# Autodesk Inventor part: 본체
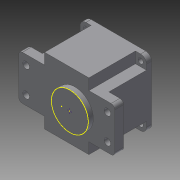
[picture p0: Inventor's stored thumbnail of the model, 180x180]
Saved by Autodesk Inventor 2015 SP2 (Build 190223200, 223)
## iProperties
Created: 2015-06
Part Number: 본체
Material: 일반
Document SubType Name: Modeling
Designer: AMC
Density: 1 g/cm^3
Appearance: 기본값
Author: AMC
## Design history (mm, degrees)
sketch "스케치3"
  geometry: L1 (30, 45)-(-30, 45); L2 (-65, 30)-(-65, -30); L3 (-30, -45)-(30, -45); L4 (65, -30)-(65, 30); L5 (30, 45)-(30, 30); L6 (30, 30)-(65, 30); L7 (65, -30)-(30, -30); L8 (30, -30)-(30, -45); L9 (-30, -45)-(-30, -30); L10 (-30, -30)-(-65, -30); L11 (-30, 45)-(-30, 30); L12 (-30, 30)-(-65, 30); 5 further points
  constraints: 24 end point, 6 point on line, 4 midpoint, 4 parallel, 3 perpendicular, 2 horizontal alignment, 2 vertical alignment, 1 collinear, 1 horizontal, 1 vertical
  dimensions: "d10" = 60 distance of L1.start L1.end; "d11" = 60 distance of L3.start L3.end; "d12" = 60 distance of L4.start L4.end; "d14" = 15 distance of L1.start L5.end; "d16" = 15 distance of L7.end L3.end; "d17" = 130 distance between parallel lines of L2 L4
extrude "돌출3" new body sketch "스케치3" distance "d18" = 12; taper "d19" = 0 deg
sketch "스케치4"
  geometry: L1 (-45, 45)-(45, 45); L2 (45, 45)-(45, -45); L3 (45, -45)-(-45, -45); L4 (-45, -45)-(-45, 45); 3 further points
  constraints: 8 end point, 2 midpoint, 2 parallel, 1 horizontal, 1 horizontal alignment, 1 perpendicular, 1 vertical alignment
  dimensions: "d21" = 90 distance of L3.end L1.start; "d22" = 90 distance of L1.start L1.end
extrude "돌출4" join sketch "스케치4" distance "d23" = 51; taper "d24" = 0 deg
sketch "스케치5"
  geometry: L1 (-45, 45)-(45, 45); L2 (45, 45)-(45, -45); L3 (45, -45)-(-45, -45); L4 (-45, -45)-(-45, 45); 3 further points
  constraints: 8 end point, 2 midpoint, 2 parallel, 1 horizontal, 1 horizontal alignment, 1 perpendicular, 1 vertical alignment
  dimensions: "d25" = 90 distance of L1.start L1.end; "d26" = 90 distance of L3.end L1.start
extrude "돌출5" join sketch "스케치5" distance "d27" = 7; taper "d28" = 0 deg
fillet "모깎기2" dims "d30" = 5
sketch "스케치6"
  geometry: L1 (-30, 45)-(30, 45) reference; L2 (45, 30)-(60, 30) reference; L3 (65, 25)-(65, -25) reference; L4 (60, -30)-(45, -30) reference; L5 (30, -45)-(-30, -45) reference; L6 (-45, -30)-(-60, -30) reference; L7 (-65, -25)-(-65, 25) reference; L8 (-60, 30)-(-45, 30) reference; L9 (-45, -45)-(-45, -30) reference; L10 (-30, -30)-(-45, -30) reference; L11 (-30, -45)-(-30, -30) reference; L12 (30, -30)-(30, -45) reference; L13 (45, -30)-(30, -30) reference; L14 (45, -30)-(45, -45) reference; L15 (45, -45)-(30, -45) reference; L16 (-30, -45)-(-45, -45) reference; L17 (-45, -30)-(-45, 30) reference; L18 (45, 30)-(45, -30) reference; L19 (30, 30)-(45, 30) reference; L20 (30, 45)-(30, 30) reference; L21 (-30, 30)-(-30, 45) reference; L22 (-45, 30)-(-30, 30) reference; L23 (-45, 30)-(-45, 45) reference; L24 (-45, 45)-(-30, 45) reference; L25 (45, 45)-(45, 30) reference; L26 (30, 45)-(45, 45) reference; C1 r 4.5 at (55, 17.5); A1 r 5 centre (60, 25) between (65, 25) and (60, 30) reference; A2 r 5 centre (60, -25) between (60, -30) and (65, -25) reference; A3 r 5 centre (-60, -25) between (-65, -25) and (-60, -30) reference; A4 r 5 centre (-60, 25) between (-60, 30) and (-65, 25) reference; 1 further point
  constraints: 1 centre point
  dimensions: "d32" = 9 diameter of C1; "d33" = 10 distance from line of L3 C1.centre; "d34" = 12.5 distance from line of L2 C1.centre
extrude "돌출6" cut sketch "스케치6" stored distance "d35" = 7; taper "d36" = 0 deg
sketch "스케치7"
  geometry: L1 (-45, -45)-(-45, 45) reference; L2 (-45, 45)-(45, 45) reference; L3 (45, 45)-(45, -45) reference; L4 (45, -45)-(-45, -45) reference; C1 r 3.5 at (37, 37); 2 further points
  constraints: 1 centre point, 1 coincident
  dimensions: "d37" = 7 diameter of C1
extrude "돌출7" cut sketch "스케치7" distance "d38" = 20; taper "d39" = 0 deg
sketch "스케치10"
  geometry: 2 further points
  constraints: 1 coincident
hole "구멍1" sketch "스케치10" at (0, 0) diameter "d48" = 78; stored, may be unused: countersink angle "d52" = 90 deg, drill point angle "d54" = 0 deg; dims "d49" = 6, "d50" = 80, "d51" = 9, "d53" = 61
sketch "스케치11"
  geometry: L1 (-45, -45)-(-45, -30) reference; L2 (-30, -30)-(-45, -30) reference; L3 (-30, -45)-(-30, -30) reference; L4 (30, -45)-(-30, -45) reference; L5 (30, -30)-(30, -45) reference; L6 (45, -30)-(30, -30) reference; L7 (45, -30)-(45, -45) reference; L8 (45, -45)-(30, -45) reference; L9 (-30, -45)-(-45, -45) reference; L10 (-45, -30)-(-45, 30) reference; L11 (-60, 30)-(-45, 30) reference; L12 (-65, -25)-(-65, 25) reference; L13 (-45, -30)-(-60, -30) reference; L14 (60, -30)-(45, -30) reference; L15 (45, 30)-(45, -30) reference; L16 (30, 30)-(45, 30) reference; L17 (30, 45)-(30, 30) reference; L18 (30, 45)-(45, 45) reference; L19 (45, 45)-(45, 30) reference; L20 (45, 30)-(60, 30) reference; L21 (65, 25)-(65, -25) reference; L22 (-45, 30)-(-45, 45) reference; L23 (-45, 45)-(-30, 45) reference; L24 (-30, 45)-(30, 45) reference; L25 (-45, 30)-(-30, 30) reference; L26 (-30, 30)-(-30, 45) reference; L27 (-45, 45)-(-30, 45); L28 (-30, 45)-(-30, 30); L29 (-30, 30)-(-45, 30); L30 (-45, 30)-(-45, 45); C1 r 39 at (0, 0) reference; C2 r 4.5 at (-55, 17.5) reference; C3 r 4.5 at (-55, -17.5) reference; C4 r 4.5 at (55, 17.5) reference; C5 r 4.5 at (55, -17.5) reference; A1 r 5 centre (-60, 25) between (-60, 30) and (-65, 25) reference; A2 r 5 centre (-60, -25) between (-65, -25) and (-60, -30) reference; A3 r 5 centre (60, 25) between (65, 25) and (60, 30) reference; A4 r 5 centre (60, -25) between (60, -30) and (65, -25) reference; 1 further point
  constraints: 8 end point, 2 parallel, 1 horizontal, 1 perpendicular
extrude "돌출9" cut sketch "스케치11" distance "d55" = 51; taper "d56" = 0 deg
sketch "스케치13"
  geometry: L1 (-45, -45)-(-45, -30) reference; L2 (-30, -30)-(-45, -30) reference; L3 (-30, -45)-(-30, -30) reference; L4 (30, -45)-(-30, -45) reference; L5 (30, -30)-(30, -45) reference; L6 (45, -30)-(30, -30) reference; L7 (45, -30)-(45, -45) reference; L8 (45, -45)-(30, -45) reference; L9 (-30, -45)-(-45, -45) reference; L10 (-45, -30)-(-45, 30) reference; L11 (-60, 30)-(-45, 30) reference; L12 (-65, -25)-(-65, 25) reference; L13 (-45, -30)-(-60, -30) reference; L14 (60, -30)-(45, -30) reference; L15 (45, 30)-(45, -30) reference; L16 (30, 30)-(45, 30) reference; L17 (30, 45)-(30, 30) reference; L18 (-30, 45)-(30, 45) reference; L19 (-30, 30)-(-30, 45) reference; L20 (-45, 30)-(-30, 30) reference; L21 (65, 25)-(65, -25) reference; L22 (45, 30)-(60, 30) reference; L23 (45, 45)-(45, 30) reference; L24 (30, 45)-(45, 45) reference; L25 (30, 45)-(45, 45); L26 (45, 45)-(45, 30); L27 (45, 30)-(30, 30); L28 (30, 30)-(30, 45); C1 r 39 at (0, 0) reference; C2 r 4.5 at (-55, 17.5) reference; C3 r 4.5 at (-55, -17.5) reference; C4 r 4.5 at (55, 17.5) reference; C5 r 4.5 at (55, -17.5) reference; A1 r 5 centre (-60, 25) between (-60, 30) and (-65, 25) reference; A2 r 5 centre (-60, -25) between (-65, -25) and (-60, -30) reference; A3 r 5 centre (60, -25) between (60, -30) and (65, -25) reference; A4 r 5 centre (60, 25) between (65, 25) and (60, 30) reference; 1 further point
  constraints: 8 end point, 2 parallel, 1 horizontal, 1 perpendicular
extrude "돌출10" cut sketch "스케치13" distance "d57" = 51; taper "d58" = 0 deg
sketch "스케치14"
  geometry: L1 (-45, -45)-(-45, -30) reference; L2 (-30, -30)-(-45, -30) reference; L3 (-30, -45)-(-30, -30) reference; L4 (30, -45)-(-30, -45) reference; L5 (30, -30)-(30, -45) reference; L6 (45, -30)-(30, -30) reference; L7 (45, -30)-(45, -45) reference; L8 (45, -45)-(30, -45) reference; L9 (-30, -45)-(-45, -45) reference; L10 (-45, -30)-(-45, 30) reference; L11 (-60, 30)-(-45, 30) reference; L12 (-65, -25)-(-65, 25) reference; L13 (-45, -30)-(-60, -30) reference; L14 (60, -30)-(45, -30) reference; L15 (45, 30)-(45, -30) reference; L16 (30, 30)-(45, 30) reference; L17 (30, 45)-(30, 30) reference; L18 (-30, 45)-(30, 45) reference; L19 (-30, 30)-(-30, 45) reference; L20 (-45, 30)-(-30, 30) reference; L21 (65, 25)-(65, -25) reference; L22 (45, 30)-(60, 30) reference; L23 (-45, -30)-(-30, -30); L24 (-30, -30)-(-30, -45); L25 (-30, -45)-(-45, -45); L26 (-45, -45)-(-45, -30); L27 (30, -30)-(45, -30); L28 (45, -30)-(45, -45); L29 (45, -45)-(30, -45); L30 (30, -45)-(30, -30); C1 r 39 at (0, 0) reference; C2 r 4.5 at (-55, 17.5) reference; C3 r 4.5 at (-55, -17.5) reference; C4 r 4.5 at (55, 17.5) reference; C5 r 4.5 at (55, -17.5) reference; A1 r 5 centre (-60, 25) between (-60, 30) and (-65, 25) reference; A2 r 5 centre (-60, -25) between (-65, -25) and (-60, -30) reference; A3 r 5 centre (60, -25) between (60, -30) and (65, -25) reference; A4 r 5 centre (60, 25) between (65, 25) and (60, 30) reference; 1 further point
  constraints: 16 end point, 4 parallel, 2 horizontal, 2 perpendicular
extrude "돌출11" cut sketch "스케치14" distance "d59" = 51; taper "d60" = 0 deg
fillet "모깎기4" dims "d61" = 8
sketch "스케치22"
  geometry: L1 (0, 0)-(-71.893, 0); L2 (0, 0)-(-54.837, 54.837); L3 (-21.763, 27.411)-(-24.429, 30.401); L4 (-27.411, 21.763)-(-30.401, 24.429); A1 r 35 centre (0, 0) between (-24.749, 24.749) and (-21.763, 27.411); A2 r 4 centre (-24.749, 24.749) between (-27.411, 21.763) and (-21.763, 27.411); A3 r 39 centre (0, 0) between (-24.429, 30.401) and (-30.401, 24.429) reference
  constraints: 8 end point, 7 point on circle, 2 centre point, 2 tangent, 1 coincident, 1 horizontal, 1 point on line
  dimensions: "d109" = 45 deg angle of L1 L2; "d110" = 70 diameter of A1; "d111" = 8 diameter of A2
extrude "돌출15" join sketch "스케치22" distance "d112" = 51; taper "d113" = 0 deg
fillet "모깎기7" dims "d114" = 4
fillet "모깎기8" dims "d118" = 2
sketch "스케치23"
  geometry: A1 r 20.5 centre (-11, 0) between (8.117, 7.402) and (8.117, -7.402); A2 r 14 centre (20, 0) between (8.117, -7.402) and (8.117, 7.402); 1 further point
  constraints: 4 point on circle, 2 centre point, 2 horizontal alignment
  dimensions: "d119" = 41 diameter of A1; "d120" = 11 distance of point (0, 0) A1.centre; "d121" = 28 diameter of A2; "d122" = 20 distance of point (0, 0) A2.centre
extrude "돌출16" join sketch "스케치23" distance "d123" = 7; taper "d124" = 0 deg
sketch "스케치24"
  geometry: C1 r 25 at (11, 0); 1 further point
  constraints: 1 centre point, 1 horizontal alignment
  dimensions: "d125" = 50 diameter of C1; "d126" = 11 distance of point (0, 0) C1.centre
extrude "돌출17" join sketch "스케치24" distance "d127" = 7; taper "d128" = 0 deg
sketch "스케치25"
  geometry: C1 r 25 at (0, 0) reference; 2 further points
  constraints: 1 coincident
  node "절단 모서리 투영12"
node "솔리드2"
mirror "대칭1"
mirror "대칭2"
mirror "대칭3"
mirror "대칭4"
pattern_circular "원형 패턴2" dims angle "d116" = 360 deg
node "절단 모서리 투영2"
node "절단 모서리 투영3"
node "절단 모서리 투영7"
node "절단 모서리 투영8"
node "절단 모서리 투영9"
other parameters: "d93" = 7
